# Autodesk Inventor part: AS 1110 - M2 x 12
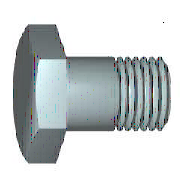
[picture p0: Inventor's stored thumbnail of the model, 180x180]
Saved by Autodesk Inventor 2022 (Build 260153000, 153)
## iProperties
Created: 2021-02
Part Number: AS 1110 - M2 x 12
Material: Acciaio, Dolce
Description: Bulloni e viti di precisione esagonali metrici ISO
Document SubType Name: Modeling
Standard: AS 1110
Designer: admin
Standards Organization: AS
Language: it-IT
Size Designation: M2 x 12
Categories: <MemberInstance><Categories><Category DisplayName="Elementi di fissaggio" InternalName="e4da775c-781d-43d5-af7c-5136215cf5a6" Mnemonic="FSTN"><Category DisplayN
Density: 7.85 g/cm^3
Appearance: Semilucidato
IsCustomPart: 0
Author: admin
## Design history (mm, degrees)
sketch "Schizzo1"
  geometry: L1 (0, 2)-(0, 1); L2 (1.2, 1)-(12, 1); L3 (12, 1)-(12, 0); L4 (12, 0)-(-0.001, 0); L5 (-2.401, 0)-(14.4, 0) reference; L6 (-0.001, 0)-(-0.001, 2); L7 (-0.001, 2)-(0, 2); L8 (1.2, 1)-(0.955, 1); L9 (0.955, 1)-(0, 1); L10 (0, -0.4)-(0, 2.4) reference
  constraints: 16 end point, 2 collinear, 2 perpendicular, 1 parallel
  dimensions: "d0" = 12 distance between parallel lines of L3 L1 (= NLG); "d1" = 10.8 distance from line of L2.start L3 (= GEL); "d2" = 2 diameter of L2 L4 (= GD); "d9" = 0.0011 distance between parallel lines of L6 L1 (computed from SD); "d10" = 4 diameter of L7 L4 (= SD2); "d13" = 0.24548 distance of L2.start L8.end (computed from GAL); "d14" = 2 diameter of L9 L4 (= BDM)
revolve "Corpo" sketch "Schizzo1" stored, may be unused: angle "d12" = 90 deg
sketch "Schizzo2"
  geometry: L1 (0, 2.309)-(2, 1.155); L2 (2, 1.155)-(2, -1.155); L3 (2, -1.155)-(0, -2.309); L4 (0, -2.309)-(-2, -1.155); L5 (-2, -1.155)-(-2, 1.155); L6 (-2, 1.155)-(0, 2.309); 2 further points
  constraints: 12 end point, 1 coincident, 1 vertical, 11 other
  dimensions: "d11" = 4 distance between parallel lines of L5 L2 (= SW)
extrude "Testa" join sketch "Schizzo2" distance "d3" = 1.399 (= KOH - SD); taper "d4" = 0 deg
sketch "Schizzo4"
  geometry: L1 (-1.4, 2)-(-1.4, 2.309); L2 (-1.4, 2.309)-(-1.221, 2.309); L3 (-1.221, 2.309)-(-1.4, 2); L4 (-1.68, 0)-(0.279, 0) reference; L5 (-0.001, 2.309)-(-1.4, 2.309) reference; L6 (-1.4, 1.155)-(-1.4, 2.309) reference
  constraints: 6 end point, 2 collinear, 1 perpendicular, 1 vertical
  dimensions: "d5" = 30 deg angle of L3 L1 (= ANG1); "d19" = 4 diameter of L1.start L4 (= SW0)
revolve "Smusso1" sketch "Schizzo4" stored, may be unused: angle "d21" = 90 deg
workplane "Work Plane1"
body "Solid1"
feature "Filettatura" dims "d15" = 10.8 (= GEL), "d16" = 0
chamfer "Smusso2" distance "d6" = 0.24538 (= -0.5 x SPD + 0.5 x GD); stored, may be unused: second distance "d7" = 0.24548 (computed from GUL), angle "d55" = 45 deg
other parameters: "NLG" = 12 [user parameter; used in 1 equation term], "GD" = 2 (= NND) [user parameter; used in 2 equation terms], "BDM" = 2 (= NND) [user parameter; used in 1 equation term], "KOH" = 1.4 [user parameter; used in 1 equation term], "GEL" = 10.8 [user parameter; used in 2 equation terms], "SW" = 4 [user parameter; used in 5 equation terms], "SW0" = 4 (= SW) [user parameter; used in 1 equation term], "SPD" = 1.50924 (= NND - 1.2269 x PTC) [user parameter; used in 1 equation term], "SD2" = 4 (= SW) [user parameter; used in 1 equation term], "SD" = 0.001 [user parameter; used in 3 equation terms], "ANG1" = 30 deg [user parameter; used in 1 equation term], "GAL" = 0.24538 (= 0.61345 x PTC) [user parameter; used in 1 equation term], "GUL" = 0.24538 (= 0.61345 x PTC) [user parameter; used in 1 equation term], "d8" = 0, "RR" = 0.001 [user parameter], "d57" = 0, "d58" = 0, "TPU" = 25 (computed from PTC) [user parameter], "WFT" = 0.001 (= SD) [user parameter], "GD1" = 1.50924 (= THREADDIA - 1.2269 x PTC) [user parameter], "THREADDIA" = 2 [user parameter; used in 1 equation term], "SDH" = 4 (= SW) [user parameter], "TOA" = 30 deg [user parameter], "FAWI" = 45 deg [user parameter], "PTC" = 0.4 [user parameter; used in 5 equation terms], "NND" = 2 [user parameter; used in 3 equation terms], "E0" = 4.62 (= 1.155 x SW) [user parameter]
